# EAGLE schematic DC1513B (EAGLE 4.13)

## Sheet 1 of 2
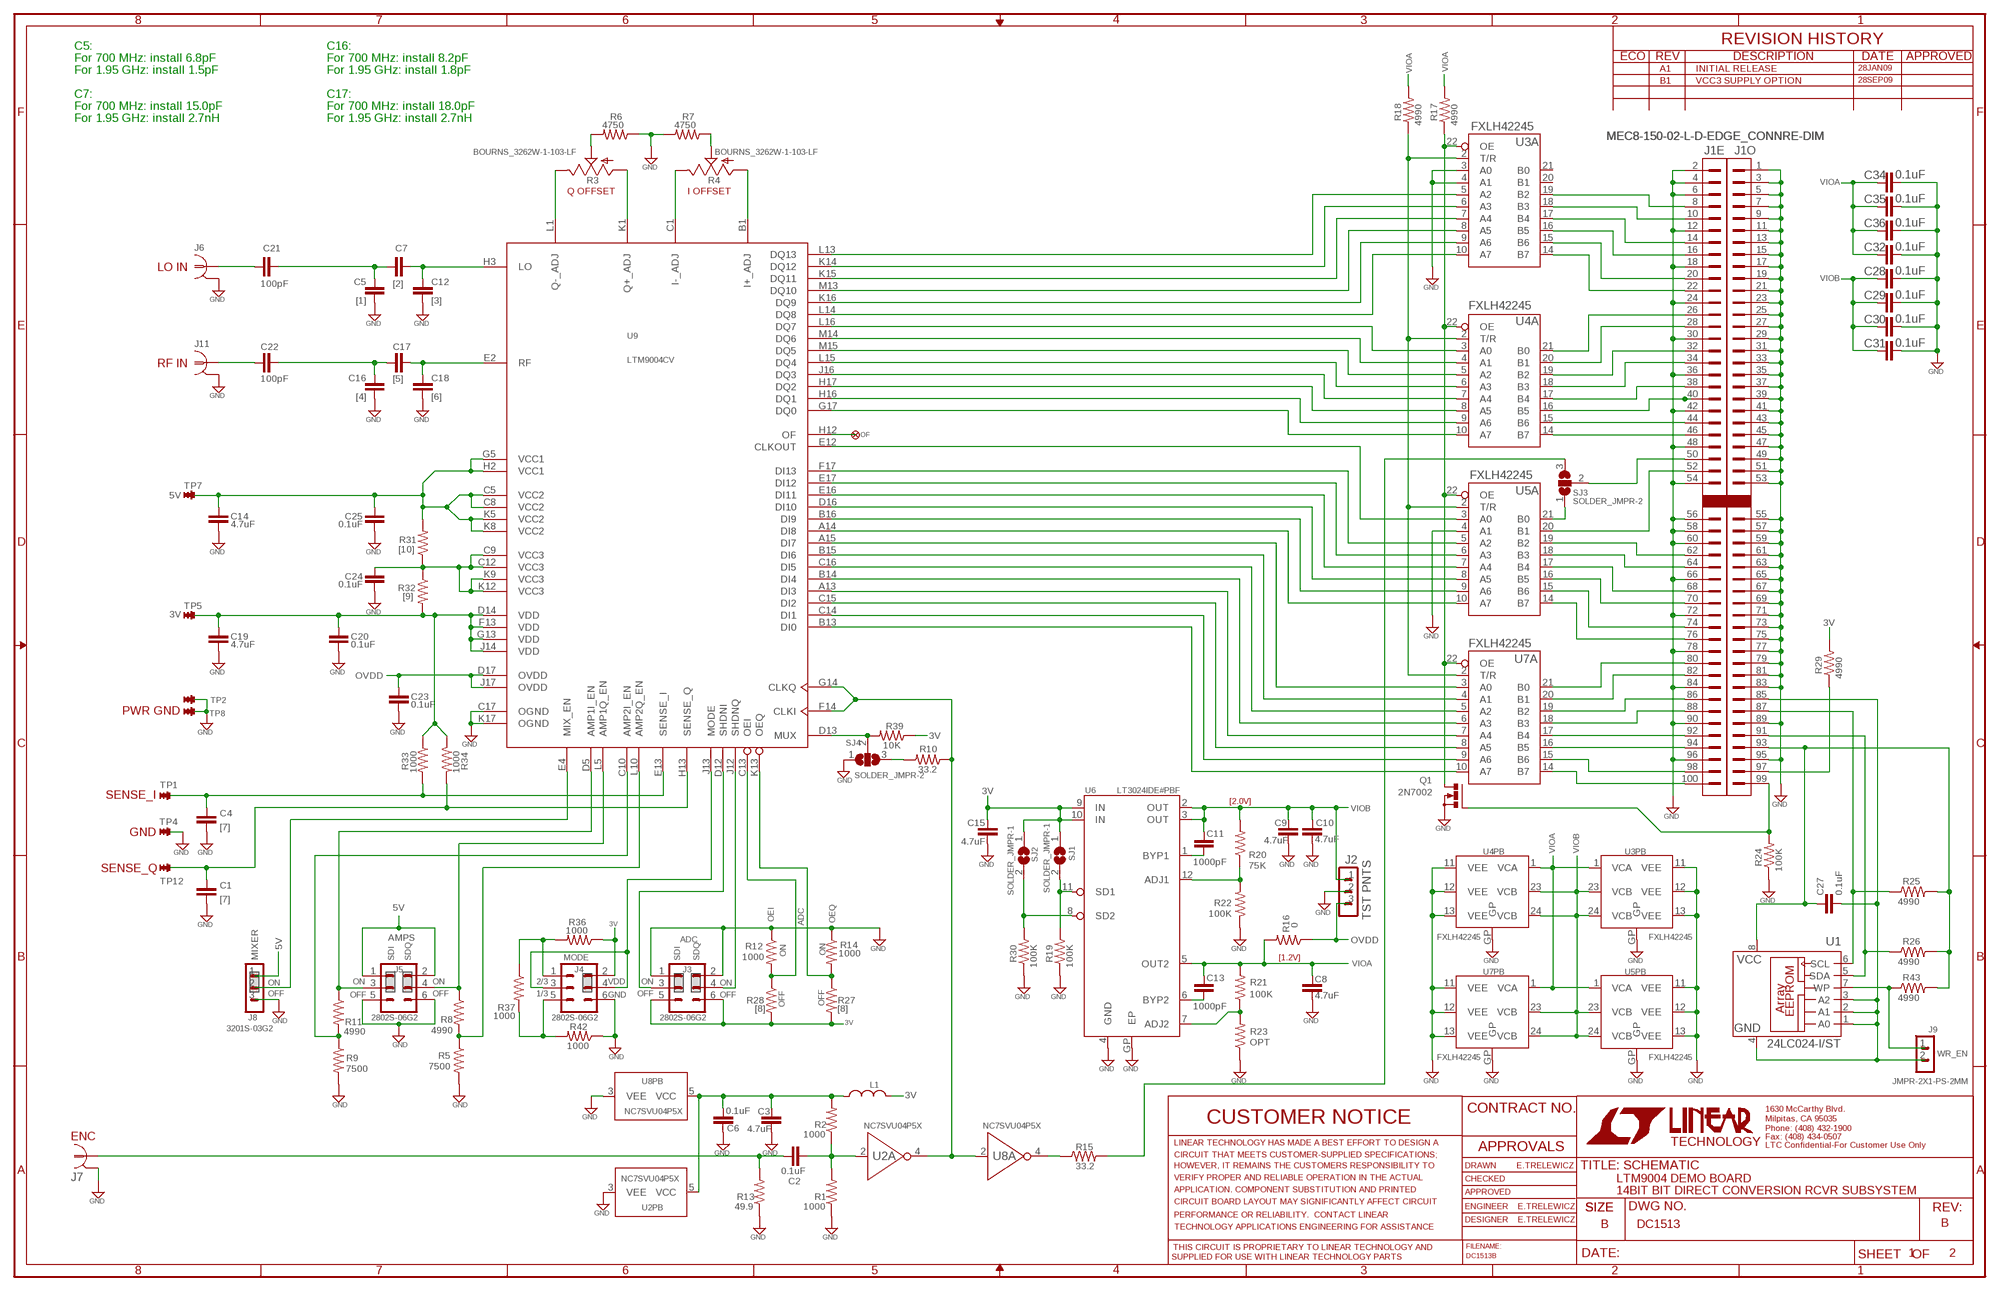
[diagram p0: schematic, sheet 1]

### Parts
C1  [7]  CAP-NP-SMT-C0402  [C0402]
C2  0.1uF  CAP-NP-SMT-C0402  [C0402]
C3  4.7uF  CAP-NP-SMT-C0805  [C0805]
C4  [7]  CAP-NP-SMT-C0402  [C0402]
C5  [1]  CAP-NP-SMT-C0402  [C0402]
C6  0.1uF  CAP-NP-SMT-C0402  [C0402]
C7  [2]  CAP-NP-SMT-C0402  [C0402]
C8  4.7uF  CAP-NP-SMT-C0805  [C0805]
C9  4.7uF  CAP-NP-SMT-C0805  [C0805]
C10  4.7uF  CAP-NP-SMT-C0805  [C0805]
C11  1000pF  CAP-NP-SMT-C0402  [C0402]
C12  [3]  CAP-NP-SMT-C0402  [C0402]
C13  1000pF  CAP-NP-SMT-C0402  [C0402]
C14  4.7uF  CAP-NP-SMT-C0805  [C0805]
C15  4.7uF  CAP-NP-SMT-C0805  [C0805]
C16  [4]  CAP-NP-SMT-C0402  [C0402]
C17  [5]  CAP-NP-SMT-C0402  [C0402]
C18  [6]  CAP-NP-SMT-C0402  [C0402]
C19  4.7uF  CAP-NP-SMT-C0805  [C0805]
C20  0.1uF  CAP-NP-SMT-C0603  [C0603]
C21  100pF  CAP-NP-SMT-C0402  [C0402]
C22  100pF  CAP-NP-SMT-C0402  [C0402]
C23  0.1uF  CAP-NP-SMT-C0603  [C0603]
C24  0.1uF  CAP-NP-SMT-C0402  [C0402]
C25  0.1uF  CAP-NP-SMT-C0402  [C0402]
C27  0.1uF  CAP-NP-SMT-C0402  [C0402]
C28  0.1uF  CAP-NP-SMT-C0402  [C0402]
C29  0.1uF  CAP-NP-SMT-C0402  [C0402]
C30  0.1uF  CAP-NP-SMT-C0402  [C0402]
C31  0.1uF  CAP-NP-SMT-C0402  [C0402]
C32  0.1uF  CAP-NP-SMT-C0402  [C0402]
C34  0.1uF  CAP-NP-SMT-C0402  [C0402]
C35  0.1uF  CAP-NP-SMT-C0402  [C0402]
C36  0.1uF  CAP-NP-SMT-C0402  [C0402]
J1  MEC8-150-02-L-D-EDGE_CONNRE-DIM  [MEC8-150-02-L-D-EDGE_CONN-NEW-ORIGIN]
J2  TST PNTS  JMPR-3X1-PS100MIL  [HDR-3X1PS-100MIL]
J3  2802S-06G2  HDR-3X2-PS2MM  [HDR-3X2PS-2MM]
J4  2802S-06G2  HDR-3X2-PS2MM  [HDR-3X2PS-2MM]
J5  2802S-06G2  HDR-3X2-PS2MM  [HDR-3X2PS-2MM]
J6  RF_CONN-SMA-FEMALE-EDGE-MNT  [SMA-FEMALE-EDGE-MNT]
J7  RF_CONN-SMA-FEMALE-EDGE-MNT  [SMA-FEMALE-EDGE-MNT]
J8  3201S-03G2  JMPR-3X1-PS2MM  [HDR-3X1PS-2MM]
J9  JMPR-2X1-PS-2MM  [HDR-2X1PS-2MM]
J11  RF_CONN-SMA-FEMALE-EDGE-MNT  [SMA-FEMALE-EDGE-MNT]
L1  IND-CER-SMT-0603  [L0603]
OF  TSTPNT10MIL  [VIA-10MIL]
Q1  2N7002  MOSFET-N-SOT23-2N7002  [SOT23]
R1  1000  RES-R0402  [R0402]
R2  1000  RES-R0402  [R0402]
R3  BOURNS_3262W-1-103-LF  [BOURNS3262W]
R4  BOURNS_3262W-1-103-LF  [BOURNS3262W]
R5  7500  RES-R0402  [R0402]
R6  4750  RES-R0402  [R0402]
R7  4750  RES-R0402  [R0402]
R8  4990  RES-R0402  [R0402]
R9  7500  RES-R0402  [R0402]
R10  33.2  RES-R0402  [R0402]
R11  4990  RES-R0402  [R0402]
R12  1000  RES-R0402  [R0402]
R13  49.9  RES-R0402  [R0402]
R14  1000  RES-R0402  [R0402]
R15  33.2  RES-R0402  [R0402]
R16  0  RES-R0805  [R0805]
R17  4990  RES-R0402  [R0402]
R18  4990  RES-R0402  [R0402]
R19  100K  RES-R0402  [R0402]
R20  75K  RES-R0402  [R0402]
R21  100K  RES-R0402  [R0402]
R22  100K  RES-R0402  [R0402]
R23  OPT  RES-R0402  [R0402]
R24  100K  RES-R0402  [R0402]
R25  4990  RES-R0402  [R0402]
R26  4990  RES-R0402  [R0402]
R27  [8]  RES-R0402  [R0402]
R28  [8]  RES-R0402  [R0402]
R29  4990  RES-R0402  [R0402]
R30  100K  RES-R0402  [R0402]
R31  [10]  RES-R0603  [R0603]
R32  [9]  RES-R0603  [R0603]
R33  1000  RES-R0402  [R0402]
R34  1000  RES-R0402  [R0402]
R36  1000  RES-R0402  [R0402]
R37  1000  RES-R0402  [R0402]
R39  10K  RES-R0402  [R0402]
R42  1000  RES-R0402  [R0402]
R43  4990  RES-R0402  [R0402]
SJ1  SOLDER_JMPR-1  [SJ1]
SJ2  SOLDER_JMPR-1  [SJ1]
SJ3  SOLDER_JMPR-2  [SJ2]
SJ4  SOLDER_JMPR-2  [SJ2]
TP1  TURRET0.063  [TURRET_MILLMAX_2308-2]
TP2  TURRET0.063  [TURRET_MILLMAX_2308-2]
TP4  TURRET0.063  [TURRET_MILLMAX_2308-2]
TP5  TURRET0.063  [TURRET_MILLMAX_2308-2]
TP7  TURRET0.063  [TURRET_MILLMAX_2308-2]
TP8  TURRET0.063  [TURRET_MILLMAX_2308-2]
TP12  TURRET0.063  [TURRET_MILLMAX_2308-2]
U1  24LC024-I/ST  24LC02ST  [TSSOP8]
U2  NC7SVU04P5X  [SC70-5]
U3  FXLH42245  [DFN_8X4]
U4  FXLH42245  [DFN_8X4]
U5  FXLH42245  [DFN_8X4]
U6  LT3024IDE#PBF  [DE12]
U7  FXLH42245  [DFN_8X4]
U8  NC7SVU04P5X  [SC70-5]
U9  LTM9004CV  [LTM9005-RNDED(204_LGA)]

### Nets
3V: C15.1 C19.1 C20.1 J3.5 J3.6 J4.2 L1.2 R27.2 R28.2 R29.2 R32.2 R33.1 R34.1 R36.1 R39.1 SJ1.1 SJ2.1 TP5.1 U6.9(IN) U6.10(IN) U9.D14(VDD) U9.F13(VDD) U9.G13(VDD) U9.J14(VDD)
5V: C14.1 C25.1 J5.1 J5.2 J8.1 R31.2 TP7.1 U9.C5(VCC2) U9.C8(VCC2) U9.G5(VCC1) U9.H2(VCC1) U9.K5(VCC2) U9.K8(VCC2)
ADC_OEI: R12.2 R28.1 U9.C13(OEI)
ADC_OEQ: R14.2 R27.1 U9.K13(OEQ)
AMP1I_EN: J5.3 R11.1 U9.D5(AMP1I_EN)
AMP1Q_EN: J5.4 R8.1 U9.L5(AMP1Q_EN)
AMP2I_EN: R9.1 R11.2 U9.C10(AMP2I_EN)
AMP2Q_EN: R5.1 R8.2 U9.L10(AMP2Q_EN)
CLKIN: C2.1 J7.1 R13.2
CLKINBUF: R10.1 U2.4(A:Y) U8.2(A:A) U9.F14(CLKI) U9.G14(CLKQ)
CLKOUT: U5.3(A:A0) U9.E12(CLKOUT)
DA0: U4.10(A:A7) U9.G17(DQ0)
DA1: U4.9(A:A6) U9.H16(DQ1)
DA2: U4.8(A:A5) U9.H17(DQ2)
DA3: U4.7(A:A4) U9.J16(DQ3)
DA4: U4.6(A:A3) U9.L15(DQ4)
DA5: U4.5(A:A2) U9.M15(DQ5)
DA6: U4.4(A:A1) U9.M14(DQ6)
DA7: U4.3(A:A0) U9.L16(DQ7)
DA8: U3.10(A:A7) U9.L14(DQ8)
DA9: U3.9(A:A6) U9.K16(DQ9)
DA10: U3.8(A:A5) U9.M13(DQ10)
DA11: U3.7(A:A4) U9.K15(DQ11)
DA12: U3.6(A:A3) U9.K14(DQ12)
DA13: U3.5(A:A2) U9.L13(DQ13)
DB0: U7.10(A:A7) U9.B13(DI0)
DB1: U7.9(A:A6) U9.C14(DI1)
DB2: U7.8(A:A5) U9.C15(DI2)
DB3: U7.7(A:A4) U9.A13(DI3)
DB4: U7.6(A:A3) U9.B14(DI4)
DB5: U7.5(A:A2) U9.C16(DI5)
DB6: U7.4(A:A1) U9.B15(DI6)
DB7: U7.3(A:A0) U9.A15(DI7)
DB8: U5.10(A:A7) U9.A14(DI8)
DB9: U5.9(A:A6) U9.B16(DI9)
DB10: U5.8(A:A5) U9.D16(DI10)
DB11: U5.7(A:A4) U9.E16(DI11)
DB12: U5.6(A:A3) U9.E17(DI12)
DB13: U5.5(A:A2) U9.F17(DI13)
GND: C1.2 C3.2 C4.2 C5.2 C6.2 C8.2 C9.2 C10.2 C12.2 C14.2 C15.2 C16.2 C18.2 C19.2 C20.2 C23.2 C24.2 C25.2 C28.2 C29.2 C30.2 C31.2 C32.2 C34.2 C35.2 C36.2 J1.1 J1.2 J1.3 J1.4 J1.5 J1.6 J1.7 J1.9 J1.11 J1.12 J1.13 J1.15 J1.17 J1.18 J1.19 J1.21 J1.23 J1.24 J1.25 J1.27 J1.29 J1.30 J1.31 J1.33 J1.35 J1.36 J1.37 J1.39 J1.41 J1.42 J1.43 J1.45 J1.47 J1.48 J1.49 J1.51 J1.53 J1.54 J1.55 J1.56 J1.57 J1.58 J1.59 J1.60 J1.61 J1.63 J1.65 J1.66 J1.67 J1.69 J1.71 J1.72 J1.73 J1.75 J1.77 J1.78 J1.79 J1.81 J1.83 J1.84 J1.89 J1.90 J1.95 J1.96 J2.2 J3.1 J3.2 J4.6 J5.5 J5.6 J6.2(GND) J7.2(GND) J8.3 J11.2(GND) Q1.2(S) R1.1 R5.2 R6.1 R7.2 R9.2 R12.1 R13.1 R14.1 R19.1 R22.1 R23.1 R24.1 R30.1 R42.1 SJ4.1 TP2.1 TP4.1 TP8.1 U2.3(PB:VEE) U3.3(A:A0) U3.4(A:A1) U3.11(PB:VEE) U3.12(PB:VEE) U3.13(PB:VEE) U3.GP(PB:GP) U4.11(PB:VEE) U4.12(PB:VEE) U4.13(PB:VEE) U4.GP(PB:GP) U5.4(A:A1) U5.11(PB:VEE) U5.12(PB:VEE) U5.13(PB:VEE) U5.GP(PB:GP) U6.4(GND) U6.GP(EP) U7.11(PB:VEE) U7.12(PB:VEE) U7.13(PB:VEE) U7.GP(PB:GP) U8.3(PB:VEE) U9.C17(OGND) U9.K17(OGND) ; also sheet 2
GND-ROM: C27.2 J1.85 J9.2 U1.1(A0) U1.2(A1) U1.3(A2) U1.4(GND)
IO_EN: J1.99 Q1.1(G) R24.2
IO_EN#: Q1.3(D) R17.1 U3.22(A:OE) U4.22(A:OE) U5.22(A:OE) U7.22(A:OE)
LO: C5.1 C7.1 C21.2
LO_IN: C17.2 C18.1 U9.E2(RF)
MIX_EN: J8.2 U9.E4(MIX_EN)
MODE: J4.3 J4.4 U9.J13(MODE)
MUX: R39.2 SJ4.2 U9.D13(MUX)
MUXCLK: R10.2 SJ4.3
N$1: C3.1 C6.1 L1.1 R2.2 U2.5(PB:VCC) U8.5(PB:VCC)
N$2: C2.2 R1.2 R2.1 U2.2(A:A)
N$3: C22.1 J11.1
N$4: C21.1 J6.1
N$5: R19.2 SJ1.2 U6.11(SD1)
N$6: R20.1 R22.2 U6.12(ADJ1)
N$10: R30.2 SJ2.2 U6.8(SD2)
N$11: J4.1 R36.2 R37.1
N$12: R15.1 U8.4(A:Y)
N$14: R3.3(C) U9.L1(Q-_ADJ)
N$15: C11.2 U6.1(BYP1)
N$16: C13.2 U6.6(BYP2)
N$18: R21.1 R23.2 U6.7(ADJ2)
N$19: R3.1(A) U9.K1(Q+_ADJ)
N$20: R4.3(C) U9.C1(I-_ADJ)
N$21: R4.1(A) U9.B1(I+_ADJ)
N$22: R18.1 U3.2(A:T/R) U4.2(A:T/R) U5.2(A:T/R) U7.2(A:T/R)
N$23: R3.2(B) R6.2
N$26: R4.2(B) R7.1
N$32: J1.46 U4.14(A:B7)
N$33: J1.44 U4.15(A:B6)
N$35: J1.40 U4.16(A:B5)
N$37: J1.38 U4.17(A:B4)
N$38: J1.34 U4.18(A:B3)
N$39: J1.32 U4.19(A:B2)
N$40: J1.28 U4.20(A:B1)
N$41: J1.26 U4.21(A:B0)
N$42: J1.22 U3.14(A:B7)
N$43: J1.20 U3.15(A:B6)
N$45: J1.16 U3.16(A:B5)
N$46: J1.14 U3.17(A:B4)
N$47: J1.10 U3.18(A:B3)
N$48: J1.8 U3.19(A:B2)
N$50: J1.50 SJ3.2
N$61: J4.5 R37.2 R42.2
N$76: J1.100 U7.14(A:B7)
N$77: J1.98 U7.15(A:B6)
N$78: J1.94 U7.16(A:B5)
N$79: J1.92 U7.17(A:B4)
N$80: J1.88 U7.18(A:B3)
N$89: J9.1 R43.1 U1.7(WP)
N$96: J1.76 U5.14(A:B7)
N$97: J1.52 U5.20(A:B1)
N$98: J1.74 U5.15(A:B6)
N$99: J1.70 U5.16(A:B5)
N$100: J1.68 U5.17(A:B4)
N$101: J1.64 U5.18(A:B3)
N$103: J1.62 U5.19(A:B2)
N$104: J1.86 U7.19(A:B2)
N$105: J1.82 U7.20(A:B1)
N$106: J1.80 U7.21(A:B0)
N$111: R15.2 SJ3.3
N$116: SJ3.1 U5.21(A:B0)
OF: OF.1 U9.H12(OF)
OVDD: C23.1 J2.3 R16.1 U9.D17(OVDD) U9.J17(OVDD)
PWR-ON: J1.97 R29.1
RF: C16.1 C17.1 C22.2
RF_IN: C7.2 C12.1 U9.H3(LO)
SCL: J1.87 R25.1 U1.6(SCL)
SDA: J1.91 R26.1 U1.5(SDA)
SENSE_I: C4.1 R33.2 TP1.1 U9.E13(SENSE_I)
SENSE_Q: C1.1 R34.2 TP12.1 U9.H13(SENSE_Q)
SHDNI: J3.3 U9.D12(SHDNI)
SHDNQ: J3.4 U9.J12(SHDNQ)
VCC3: C24.1 R31.1 R32.1 U9.C9(VCC3) U9.C12(VCC3) U9.K9(VCC3) U9.K12(VCC3)
VIOA: C8.1 C13.1 C32.1 C34.1 C35.1 C36.1 R16.2 R17.2 R18.2 R21.2 U3.1(PB:VCA) U4.1(PB:VCA) U5.1(PB:VCA) U6.5(OUT2) U7.1(PB:VCA)
VIOB: C9.1 C10.1 C11.1 C28.1 C29.1 C30.1 C31.1 J2.1 R20.2 U3.23(PB:VCB) U3.24(PB:VCB) U4.23(PB:VCB) U4.24(PB:VCB) U5.23(PB:VCB) U5.24(PB:VCB) U6.2(OUT) U6.3(OUT) U7.23(PB:VCB) U7.24(PB:VCB)
VROM: C27.1 J1.93 R25.2 R26.2 R43.2 U1.8(VCC)
Unconnected: U3.20(A:B1) U3.21(A:B0)

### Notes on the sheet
- C5: | C16:
- For 700 MHz: install 6.8pF | For 700 MHz: install 8.2pF
- A1 | INITIAL RELEASE | 28JAN09
- For 1.95 GHz: install 1.5pF | For 1.95 GHz: install 1.8pF
- B1 | VCC3 SUPPLY OPTION | 28SEP09
- C7: | C17:
- For 700 MHz: install 15.0pF | For 700 MHz: install 18.0pF
- For 1.95 GHz: install 2.7nH | For 1.95 GHz: install 2.7nH
- Q OFFSET | I OFFSET
- LO IN
- RF IN
- PWR GND
- SENSE_I
- [2.0V]
- GND
- SENSE_Q
- OEI | OEQ
- ADC
- AMPS | ADC
- ON | ON
- MIXER | SDI | SDQ | MODE | SDI | SDQ | [1.2V]
- ON | ON | ON | 2/3 | VDD | ON | ON
- OFF | OFF | OFF | 1/3 | GND | OFF | OFF
- OFF | OFF
- WR_EN
- ENC
- E.TRELEWICZ
- LTM9004 DEMO BOARD
- 14BIT BIT DIRECT CONVERSION RCVR SUBSYSTEM
- E.TRELEWICZ
- E.TRELEWICZ
- B | DC1513 | B
- 1 | 2

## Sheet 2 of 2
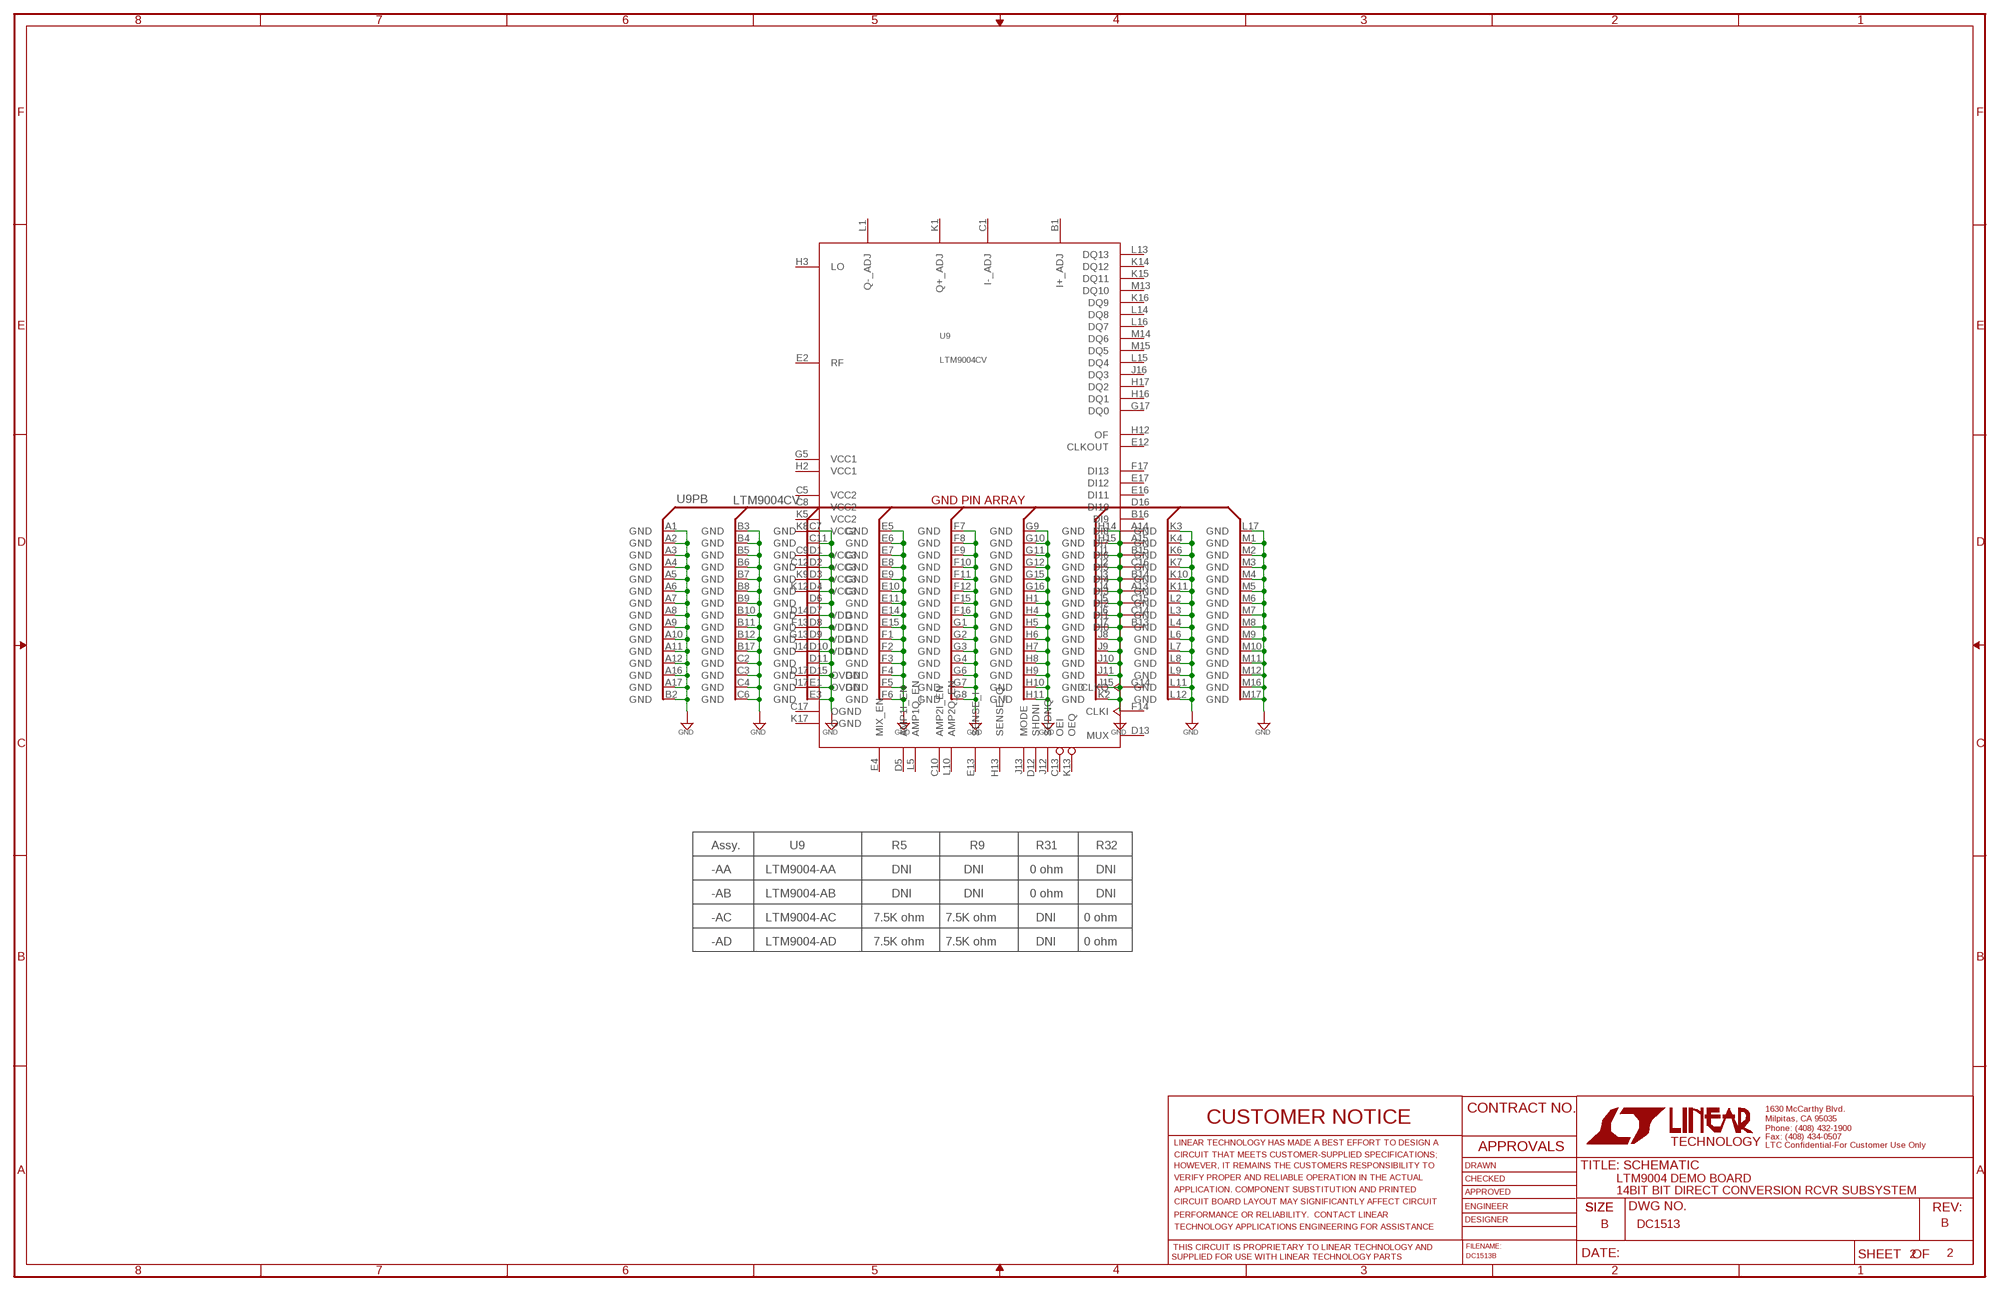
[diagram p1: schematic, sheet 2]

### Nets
GND: U9.A1(GND) U9.A2(GND) U9.A3(GND) U9.A4(GND) U9.A5(GND) U9.A6(GND) U9.A7(GND) U9.A8(GND) U9.A9(GND) U9.A10(GND) U9.A11(GND) U9.A12(GND) U9.A16(GND) U9.A17(GND) U9.B2(GND) U9.B3(GND) U9.B4(GND) U9.B5(GND) U9.B6(GND) U9.B7(GND) U9.B8(GND) U9.B9(GND) U9.B10(GND) U9.B11(GND) U9.B12(GND) U9.B17(GND) U9.C2(GND) U9.C3(GND) U9.C4(GND) U9.C6(GND) U9.C7(GND) U9.C11(GND) U9.D1(GND) U9.D2(GND) U9.D3(GND) U9.D4(GND) U9.D6(GND) U9.D7(GND) U9.D8(GND) U9.D9(GND) U9.D10(GND) U9.D11(GND) U9.D15(GND) U9.E1(GND) U9.E3(GND) U9.E5(GND) U9.E6(GND) U9.E7(GND) U9.E8(GND) U9.E9(GND) U9.E10(GND) U9.E11(GND) U9.E14(GND) U9.E15(GND) U9.F1(GND) U9.F2(GND) U9.F3(GND) U9.F4(GND) U9.F5(GND) U9.F6(GND) U9.F7(GND) U9.F8(GND) U9.F9(GND) U9.F10(GND) U9.F11(GND) U9.F12(GND) U9.F15(GND) U9.F16(GND) U9.G1(GND) U9.G2(GND) U9.G3(GND) U9.G4(GND) U9.G6(GND) U9.G7(GND) U9.G8(GND) U9.G9(GND) U9.G10(GND) U9.G11(GND) U9.G12(GND) U9.G15(GND) U9.G16(GND) U9.H1(GND) U9.H4(GND) U9.H5(GND) U9.H6(GND) U9.H7(GND) U9.H8(GND) U9.H9(GND) U9.H10(GND) U9.H11(GND) U9.H14(GND) U9.H15(GND) U9.J1(GND) U9.J2(GND) U9.J3(GND) U9.J4(GND) U9.J5(GND) U9.J6(GND) U9.J7(GND) U9.J8(GND) U9.J9(GND) U9.J10(GND) U9.J11(GND) U9.J15(GND) U9.K2(GND) U9.K3(GND) U9.K4(GND) U9.K6(GND) U9.K7(GND) U9.K10(GND) U9.K11(GND) U9.L2(GND) U9.L3(GND) U9.L4(GND) U9.L6(GND) U9.L7(GND) U9.L8(GND) U9.L9(GND) U9.L11(GND) U9.L12(GND) U9.L17(GND) U9.M1(GND) U9.M2(GND) U9.M3(GND) U9.M4(GND) U9.M5(GND) U9.M6(GND) U9.M7(GND) U9.M8(GND) U9.M9(GND) U9.M10(GND) U9.M11(GND) U9.M12(GND) U9.M16(GND) U9.M17(GND) ; also sheet 1

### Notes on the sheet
- Assy. | U9 | R5 | R9 | R31 | R32
- -AA | LTM9004-AA | DNI | DNI | 0 ohm | DNI
- -AB | LTM9004-AB | DNI | DNI | 0 ohm | DNI
- -AC | LTM9004-AC | 7.5K ohm | 7.5K ohm | DNI | 0 ohm
- -AD | LTM9004-AD | 7.5K ohm | 7.5K ohm | DNI | 0 ohm
- LTM9004 DEMO BOARD
- 14BIT BIT DIRECT CONVERSION RCVR SUBSYSTEM
- B | DC1513 | B
- 2 | 2

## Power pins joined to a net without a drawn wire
GND: J6.3(GND) J6.4(GND) J6.5(GND) J7.3(GND) J7.4(GND) J7.5(GND) J11.3(GND) J11.4(GND) J11.5(GND)

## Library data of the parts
C1-C25 C27-C32 C34-C36 = LTDB_Passives:CAP-NP-SMT-: Capacitor; Non-polar; SMT
J1 = LTDB_Connectors:MEC8-150-02-L-D-EDGE_CONN
J2 J8 = LTDB_Connectors:JMPR-3X1-PS: Jumper,3pin, point connections
J3-J5 = LTDB_Connectors:HDR-3X2-PS: Header 3x2 Pin, Straight
J6 J7 J11 = LTDB_Connectors:RF_CONN-: BNC CONNECTOR M/A COM www.macom.com distributor Farnell 149-452
J9 = LTDB_Connectors:JMPR-2X1-PS?: Header, 2x1, 2mm
L1 = LTDB_Passives:IND-CER-SMT-: Inductor,Ceramic,SMT
OF = LTDB_Connectors:TSTPNT?
Q1 = LTDB_Discretes:MOSFET-N-?-*
R1 R2 R5-R34 R36 R37 R39 R42 R43 = LTDB_Passives:RES-: Resistor; GP
R3 R4 = LTDB_Passives:BOURNS_3262?-1-*-LF: Potentiometer, Trimmer, Bourns
SJ1 SJ2 = LTDB_Connectors:SOLDER_JMPR-1
SJ3 SJ4 = LTDB_Connectors:SOLDER_JMPR-2
TP1 TP2 TP4 TP5 TP7 TP8 TP12 = LTDB_Connectors:TURRET: Turret
U1 = LTDB_ICs:24*?: I2C SEEP Memory
U2 U8 = LTDB_ICs:NC7SVU04?X: Buffer, Inverting, CMOS, Unbuffered, SMT, Single
U3-U5 U7 = LTDB_ICs:FXLH42245: Level Translater, Bidirectional, Octal
U6 = LTDB_Linear_Parts:LT3024*?#PBF: Voltage Regulator, Dual, 500/100ma, sm t
U9 = LTDB_Linear_Parts:LTM9004CV: Direct Conversion Subsystem, 14Bit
